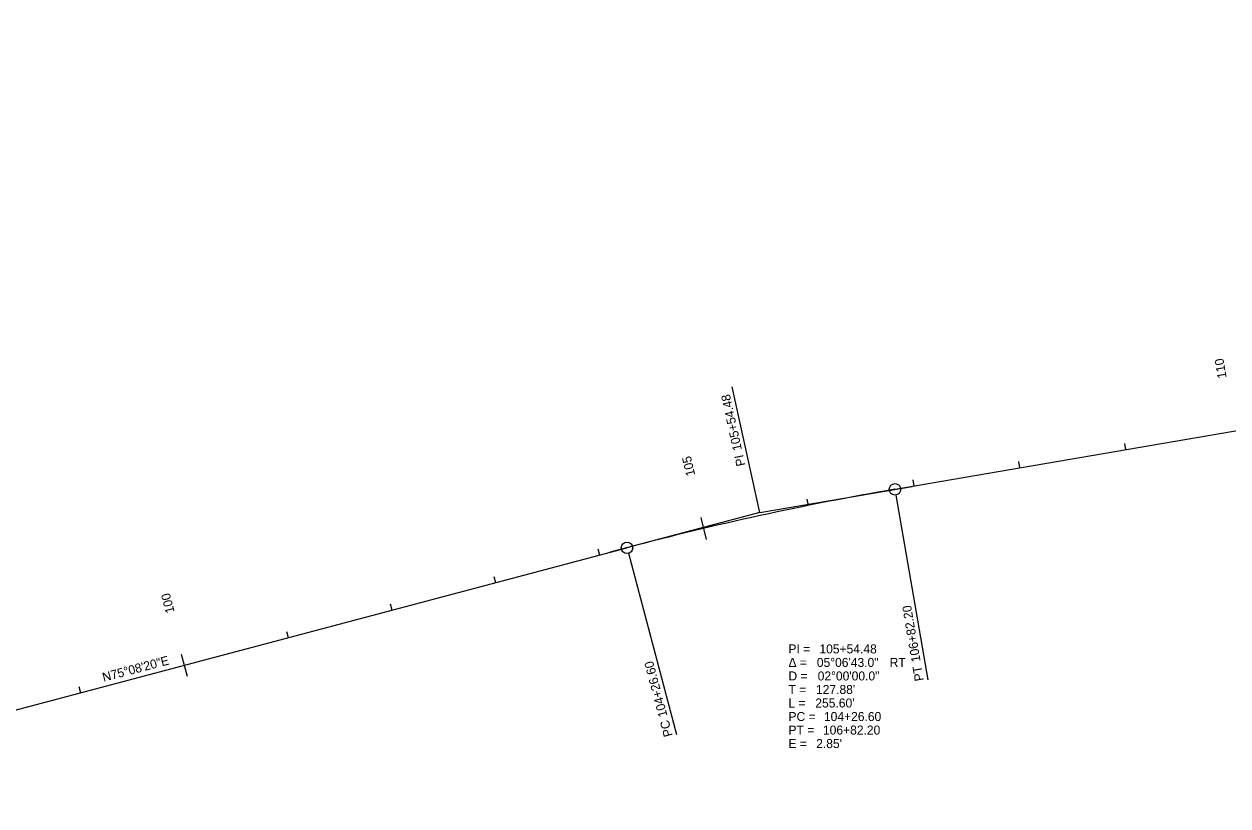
# Model space of a CAD drawing. Extents: x 1145421 to 1155673, y 2015317 to 2021442.
# Drawn here: x 1152333 to 1153454, y 2020542 to 2021270 of the extents above; entities that cross this region are included whole.
import ezdxf

# ---------------------------------------------------------------- set-up
doc = ezdxf.new("R2010")
doc.units = 0
for name, color, linetype in [('Default', 7, 'Continuous'), ('EX_CONTOUR_ANNOT_MINOR', 7, 'Continuous'), ('EX_TERRAIN', 7, 'Continuous')]:
    doc.layers.add(name, color=color, linetype=linetype)

msp = doc.modelspace()

# ---------------------------------------------------------------- linework, layer by layer
at = {"layer": 'Default'}
for p, q in [((1153144.2, 2020836.8), (1155667.4, 2021270.3)), ((1151988, 2020541.8), (1152894.6, 2020782.3))]:
    msp.add_line(p, q, dxfattribs=at)
msp.add_arc((1153629.3, 2018013.4), 2864.8, 99.7491, 104.861, dxfattribs=at)
at = {"layer": 'EX_CONTOUR_ANNOT_MINOR'}
for p, q in [((1153018.2, 2020815.1), (1152992.6, 2020932.4)), ((1152992.6, 2020932.4), (1152992.6, 2020932.4)), ((1153357.9, 2020879.6), (1153358.9, 2020873.7)), ((1153259.3, 2020862.7), (1153260.3, 2020856.7)), ((1153160.7, 2020845.7), (1153161.8, 2020839.8)), ((1153018.2, 2020815.1), (1153160.1, 2020839.5)), ((1153144.2, 2020836.8), (1153144.2, 2020836.8)), ((1153062.2, 2020827.6), (1153063.4, 2020821.7)), ((1153145.1, 2020831.5), (1153174.7, 2020659.4)), ((1153018.2, 2020815.1), (1152879, 2020778.2)), ((1152963.3, 2020810.7), (1152968.2, 2020790)), ((1152867.3, 2020781.3), (1152868.9, 2020775.5)), ((1152894.6, 2020782.3), (1152894.6, 2020782.3)), ((1152895.9, 2020777.2), (1152940.7, 2020608.4)), ((1152770.7, 2020755.7), (1152772.2, 2020749.9)), ((1152674, 2020730), (1152675.5, 2020724.2)), ((1152577.4, 2020704.4), (1152578.9, 2020698.6)), ((1152479.5, 2020683.3), (1152484.9, 2020662.7)), ((1152384, 2020653.1), (1152385.6, 2020647.3)), ((1153174.7, 2020659.4), (1153174.7, 2020659.4)), ((1152940.7, 2020608.4), (1152940.7, 2020608.4))]:
    msp.add_line(p, q, dxfattribs=at)
for centre in [(1153144.2, 2020836.8), (1152894.6, 2020782.3)]:
    msp.add_circle(centre, 5.34, dxfattribs=at)
at = {"layer": 'EX_TERRAIN'}
for p, q in [((1153144.2, 2020836.8), (1155667.4, 2021270.3)), ((1151988, 2020541.8), (1152894.6, 2020782.3))]:
    msp.add_line(p, q, dxfattribs=at)
msp.add_arc((1153629.3, 2018013.4), 2864.8, 99.7491, 104.861, dxfattribs=at)

# ---------------------------------------------------------------- texts
at = {"layer": 'EX_CONTOUR_ANNOT_MINOR'}
for s, rotation, p in [('110', 99.7491, (1153453.1, 2020940.8)), ('105+54.48', 102.305, (1153001.7, 2020873.8)), ('105', 103.393, (1152958.2, 2020850.2)), ('PI ', 102.305, (1153004.9, 2020859.3)), ('100', 104.861, (1152473.4, 2020722.6)), ('106+82.20', 99.7491, (1153168.1, 2020676.6)), ('N75°08\'20"E', 14.861, (1152407.2, 2020657.4)), ('104+26.60', 104.861, (1152932.4, 2020625.8)), ('PT', 99.7491, (1153171.1, 2020658.8)), ('PC', 104.861, (1152937.3, 2020607.4))]:
    msp.add_text(s, height=8.4, rotation=rotation, dxfattribs=at).set_placement(p)
for s, p in [('PI = ', (1153045, 2020683.9)), ('105+54.48', (1153073.8, 2020683.9)), ('Δ = ', (1153045, 2020671.3)), ('05°06\'43.0"', (1153071.4, 2020671.3)), (' RT', (1153136.1, 2020671.3)), ('D = ', (1153045, 2020658.7)), ('02°00\'00.0"', (1153072.2, 2020658.7)), ('T = ', (1153045, 2020646.1)), ("127.88'", (1153070.6, 2020646.1)), ('L = ', (1153045, 2020633.5)), ("255.60'", (1153070, 2020633.5)), ('PC = ', (1153045, 2020620.9)), ('104+26.60', (1153078, 2020620.9)), ('PT = ', (1153045, 2020608.3)), ('106+82.20', (1153077.1, 2020608.3)), ('E = ', (1153045, 2020595.7)), ("2.85'", (1153070.8, 2020595.7))]:
    msp.add_text(s, height=8.4, dxfattribs=at).set_placement(p)

doc.saveas('drawing.dxf')
